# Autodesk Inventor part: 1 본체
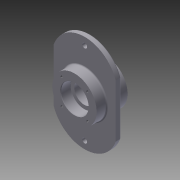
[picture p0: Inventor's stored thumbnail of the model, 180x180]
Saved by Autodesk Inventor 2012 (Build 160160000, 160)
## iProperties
Created: 2015-02
Part Number: 1 본체
Material: 알루미늄-6061
Document SubType Name: Modeling
Designer: Class3-User
Density: 2.71 g/cm^3
Mass: 1635.99 g
Surface Area: 894.151 cm^2
Volume: 603.686 cm^3
Author: Class3-User
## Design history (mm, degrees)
sketch "스케치1"
  geometry: L1 (-70, -60)-(-70, 60); L2 (70, 60)-(70, -60); L3 (70, 0)-(-70, 0); L4 (0, -36)-(0, 36); A1 r 74 centre (0, -36) between (-70, -60) and (70, -60); A2 r 74 centre (0, 36) between (70, 60) and (-70, 60); 4 further points
  constraints: 8 end point, 6 point on circle, 3 midpoint, 2 centre point, 2 parallel, 2 vertical, 1 coincident, 2 other
  dimensions: "d0" = 120 distance of L1.start L1.end; "d2" = 140 distance between parallel lines of L1 L2; "d3" = 220 distance of point (0, -110) point (0, 110)
extrude "돌출1" new body sketch "스케치1" distance "d4" = 12; taper "d5" = 0 deg
node "작업 평면1"
sketch "스케치2"
  geometry: C1 r 50 at (0, 0); 1 further point
  constraints: 1 centre point, 1 coincident
  dimensions: "d7" = 100 diameter of C1
extrude "돌출2" join sketch "스케치2" distance "d8" = 70; taper "d9" = 0 deg
sketch "스케치3"
  geometry: C1 r 50 at (0, 0) reference; C2 r 31 at (0, 0)
  constraints: 1 centre point, 1 coincident
  dimensions: "d10" = 62 diameter of C2
extrude "돌출3" cut sketch "스케치3" distance "d11" = 22; taper "d12" = 0 deg
sketch "스케치4"
  geometry: C1 r 50 at (0, 0) reference; C2 r 31 at (0, 0)
  constraints: 1 centre point, 1 coincident
  dimensions: "d13" = 62 diameter of C2
extrude "돌출4" cut sketch "스케치4" distance "d14" = 22; taper "d15" = 0 deg
sketch "스케치5"
  geometry: C1 r 31 at (0, 0) reference; C2 r 22.5 at (0, 0)
  constraints: 1 centre point, 1 coincident
  dimensions: "d16" = 45 diameter of C2
extrude "돌출5" cut sketch "스케치5" stored distance "d17" = 22; taper "d18" = 0 deg
sketch "스케치6"
  geometry: L1 (0, 41)-(0, 0); L2 (0, 0)-(28.991, 28.991); C1 r 50 at (0, 0) reference; A1 r 41 centre (0, 0) between (0, 41) and (28.991, 28.991); 1 further point
  constraints: 4 end point, 2 coincident, 2 point on circle, 1 centre point, 1 vertical
  dimensions: "d19" = 82 diameter of A1; "d20" = 45 deg angle of L1 L2
hole "구멍1" sketch "스케치6" at (28.991, 28.991) diameter "d21" = 4.917; stored, may be unused: countersink angle "d25" = 90 deg, drill point angle "d27" = 118 deg; dims "d22" = 10, "d23" = 4, "d24" = 2, "d26" = 13
sketch "스케치7"
  geometry: L1 (0, 41)-(0, 0); L2 (0, 0)-(28.991, 28.991); C1 r 50 at (0, 0) reference; A1 r 41 centre (0, 0) between (0, 41) and (28.991, 28.991); 1 further point
  constraints: 4 end point, 2 coincident, 2 point on circle, 1 centre point, 1 vertical
  dimensions: "d31" = 82 diameter of A1; "d32" = 45 deg angle of L2 L1
hole "구멍2" sketch "스케치7" at (28.991, 28.991) diameter "d33" = 4.917; stored, may be unused: countersink angle "d37" = 90 deg, drill point angle "d39" = 118 deg; dims "d34" = 10, "d35" = 4, "d36" = 2, "d38" = 13
fillet "모깎기1" dims "d43" = 0.3, "d47" = 3
chamfer "모따기1" distance "d44" = 1; stored, may be unused: second distance "d45" = 2, angle "d46" = 45 deg
sketch "스케치8"
  geometry: L1 (-70, 60)-(-70, -60) reference; L2 (70, -60)-(70, 60) reference; L3 (-53, 56.976)-(-53, -56.976); L4 (53, -56.976)-(53, 56.976); C1 r 10 at (0, 93); A1 r 74 centre (0, 36) between (70, 60) and (-70, 60) reference; A2 r 74 centre (0, -36) between (-70, -60) and (70, -60) reference; A3 r 57 centre (0, 36) between (53, 56.976) and (-53, 56.976); A4 r 57 centre (0, -36) between (-53, -56.976) and (53, -56.976); 2 further points
  constraints: 5 point on circle, 4 end point, 3 centre point, 2 coincident, 3 other
  dimensions: "d50" = 17 distance between parallel lines of L4 L2; "d51" = 20 diameter of C1
extrude "돌출6" join sketch "스케치8" distance "d52" = 5; taper "d53" = 0 deg
sketch "스케치10"
  geometry: C1 r 10 at (0, 0) reference; C2 r 5.5 at (0, 0); 1 further point
  constraints: 1 centre point, 1 coincident
  dimensions: "d55" = 11 diameter of C2
extrude "돌출7" cut sketch "스케치10" stored distance "d56" = 5; taper "d57" = 0 deg
fillet "모깎기4" dims "d58" = 3
fillet "모깎기5" dims "d59" = 3
sketch "스케치11"
  geometry: L1 (-33.183, 69.803)-(33.183, 69.803); L2 (33.183, 69.803)-(33.183, 60.197); L3 (33.183, 60.197)-(-33.183, 60.197); L4 (-33.183, 60.197)-(-33.183, 69.803); L5 (-33.183, 65)-(33.183, 65); L6 (0, 65)-(0, 0); C1 r 53 at (0, 0) reference
  constraints: 4 end point, 3 midpoint, 1 vertical, 2 other
  dimensions: "d60" = 65 distance of L6.start L6.end
feature "엠보싱1" sketch "스케치11" dims "d61" = 1, "d62" = 0
fillet "모깎기6" dims "d63" = 3
node "솔리드1"
pattern_circular "원형 패턴1" dims angle "d29" = 360 deg
pattern_circular "원형 패턴2" dims angle "d41" = 360 deg
mirror "대칭1"
other parameters: "d6" = 23
